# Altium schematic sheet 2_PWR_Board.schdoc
size 254 x 203 mm; Symbol: Altium_A; Device: Altium_A; SheetNumber: 1; SheetTotal: 5
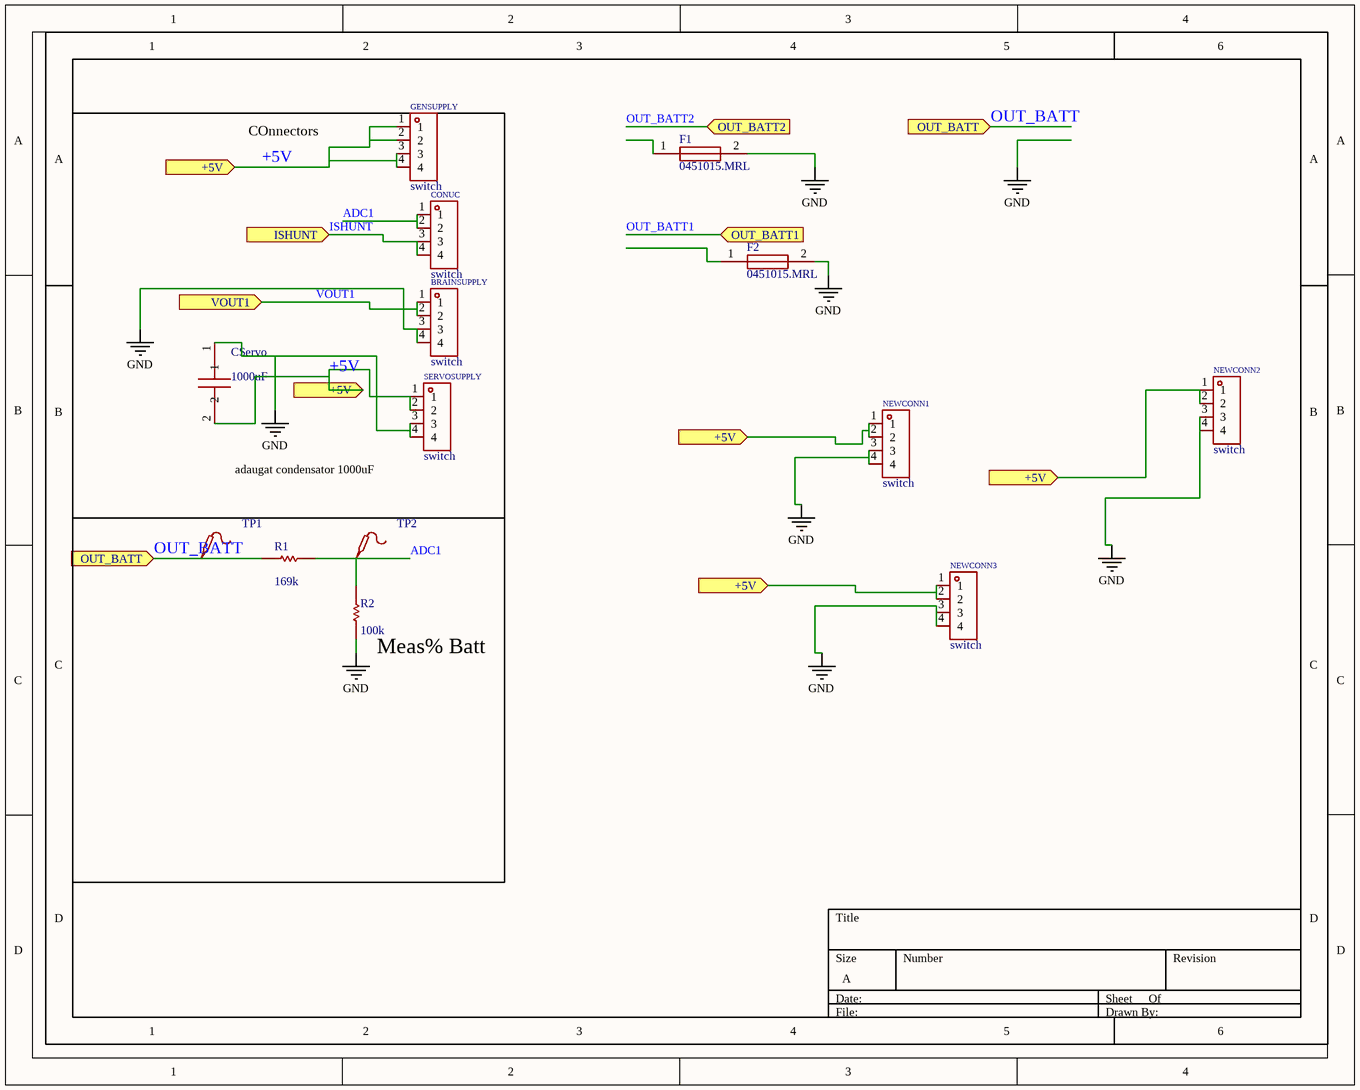
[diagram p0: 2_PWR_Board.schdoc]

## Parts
BRAINSUPPLY  switch  [1704498]  (value not drawn)
CONUC  switch  [1704498]  (value not drawn)
CServo  value 1000uF  [CAPAE1030X1050N]  (hidden comment: GCM188C71A225K)
F1  0451015.MRL  [FUSC6127X294N]  (value not drawn)
F2  0451015.MRL  [FUSC6127X294N]  (value not drawn)
GENSUPPLY  switch  [1704498]  (value not drawn)
NEWCONN1  switch  [1704498]  (value not drawn)
NEWCONN2  switch  [1704498]  (value not drawn)
NEWCONN3  switch  [1704498]  (value not drawn)
R1  value 169k  [R0805_NEW]  (hidden comment: MCR03..PFX1051)
R2  value 100k  [R0603_NEW]  (hidden comment: MCR03...PFX7680)
SERVOSUPPLY  switch  [1704498]  (value not drawn)
TP1  Test-Point  [Test-Point-0.5mm]  (value not drawn)
TP2  Test-Point  [Test-Point-0.5mm]  (value not drawn)

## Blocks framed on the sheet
COnnectors: BRAINSUPPLY CONUC CServo GENSUPPLY SERVOSUPPLY
Meas% Batt: R1 R2 TP1 TP2

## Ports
+5V (in), ISHUNT (in), OUT_BATT1 (in), OUT_BATT2 (in), OUT_BATT (in), VOUT1 (in)

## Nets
GND: BRAINSUPPLY.3 BRAINSUPPLY.4 CServo.1 F1.2 F2.2 NEWCONN1.3 NEWCONN1.4 NEWCONN2.3 NEWCONN2.4 NEWCONN3.3 NEWCONN3.4 R2.2 SERVOSUPPLY.3 SERVOSUPPLY.4
+5V: CServo.2 GENSUPPLY.1 GENSUPPLY.2 GENSUPPLY.3 GENSUPPLY.4 NEWCONN1.1 NEWCONN1.2 NEWCONN2.1 NEWCONN2.2 NEWCONN3.1 NEWCONN3.2 SERVOSUPPLY.1 SERVOSUPPLY.2 ; port +5V
ADC1: CONUC.1 CONUC.2 R1.1 R2.1 TP2.1
ISHUNT: CONUC.3 CONUC.4 ; port ISHUNT
OUT_BATT: R1.2 TP1.1 ; port OUT_BATT
VOUT1: BRAINSUPPLY.1 BRAINSUPPLY.2 ; port VOUT1

Not connected (* = marked no-connect by the designer): F1 1; F2 1

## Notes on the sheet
- adaugat condensator 1000uF

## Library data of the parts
BRAINSUPPLY CONUC GENSUPPLY NEWCONN1-NEWCONN3 SERVOSUPPLY = HDR-F_2.54_1x4P: Manufacturer: BOOMELE(博穆精密); Symbol: 2.54-1*4P母; Convert to PCB: yes
CServo = GCM188C71A225K: C1608X7R1A225K08; Manufacturer Part Number: C1608X7R1A225K080AC; Manufacturer Name: TDK; Symbol: Cinx; Add into BOM: yes; Origin Footprint: CAPC1608X80N
F1 F2 = 0451015.MRL: Fuse; Manufacturer_Name: LITTELFUSE; Add into BOM: yes
R1 = MCR03..PFX1051: Resistor; Symbol: Res1; Origin Footprint 2: AXIAL-0.3; Add into BOM: yes; Origin Footprint 1: RESC1608X55N
R2 = MCR03...PFX7680: Resistor; Symbol: Res1; Origin Footprint 2: AXIAL-0.3; Add into BOM: yes; Origin Footprint 1: RESC1608X55N
TP1 TP2 = Test-Point: Test Point 测试点; Add into BOM: yes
